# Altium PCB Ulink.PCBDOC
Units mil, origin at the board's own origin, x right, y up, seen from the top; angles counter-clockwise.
Board outline 1950 x 3950 mil, 2 copper layers (Top Layer, Bottom Layer); 42 components, 78 nets, 284 pads, 118 vias.
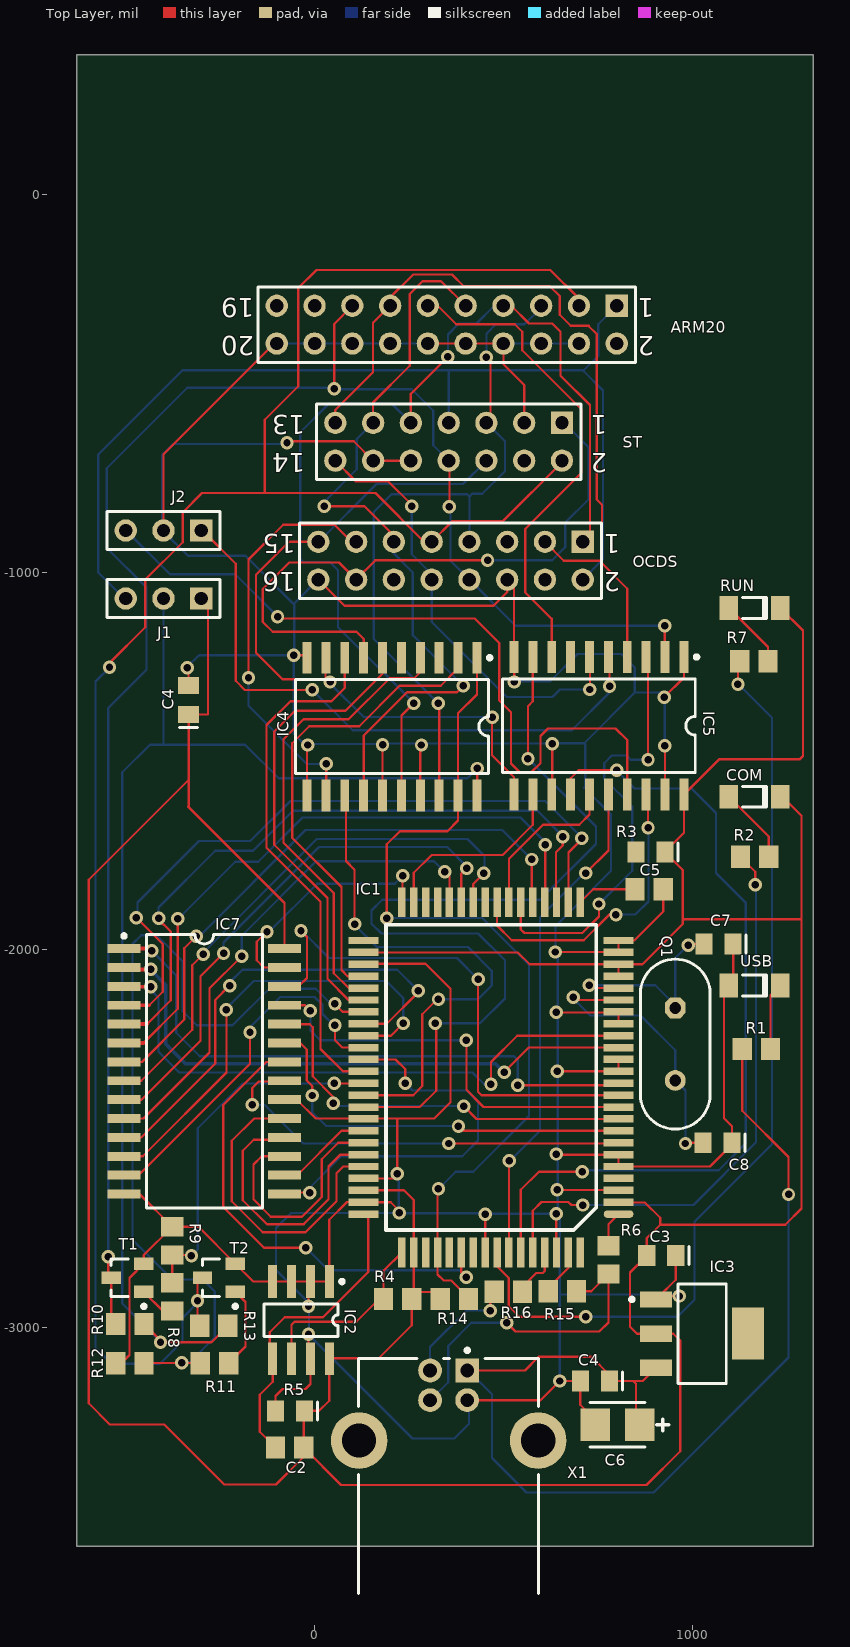
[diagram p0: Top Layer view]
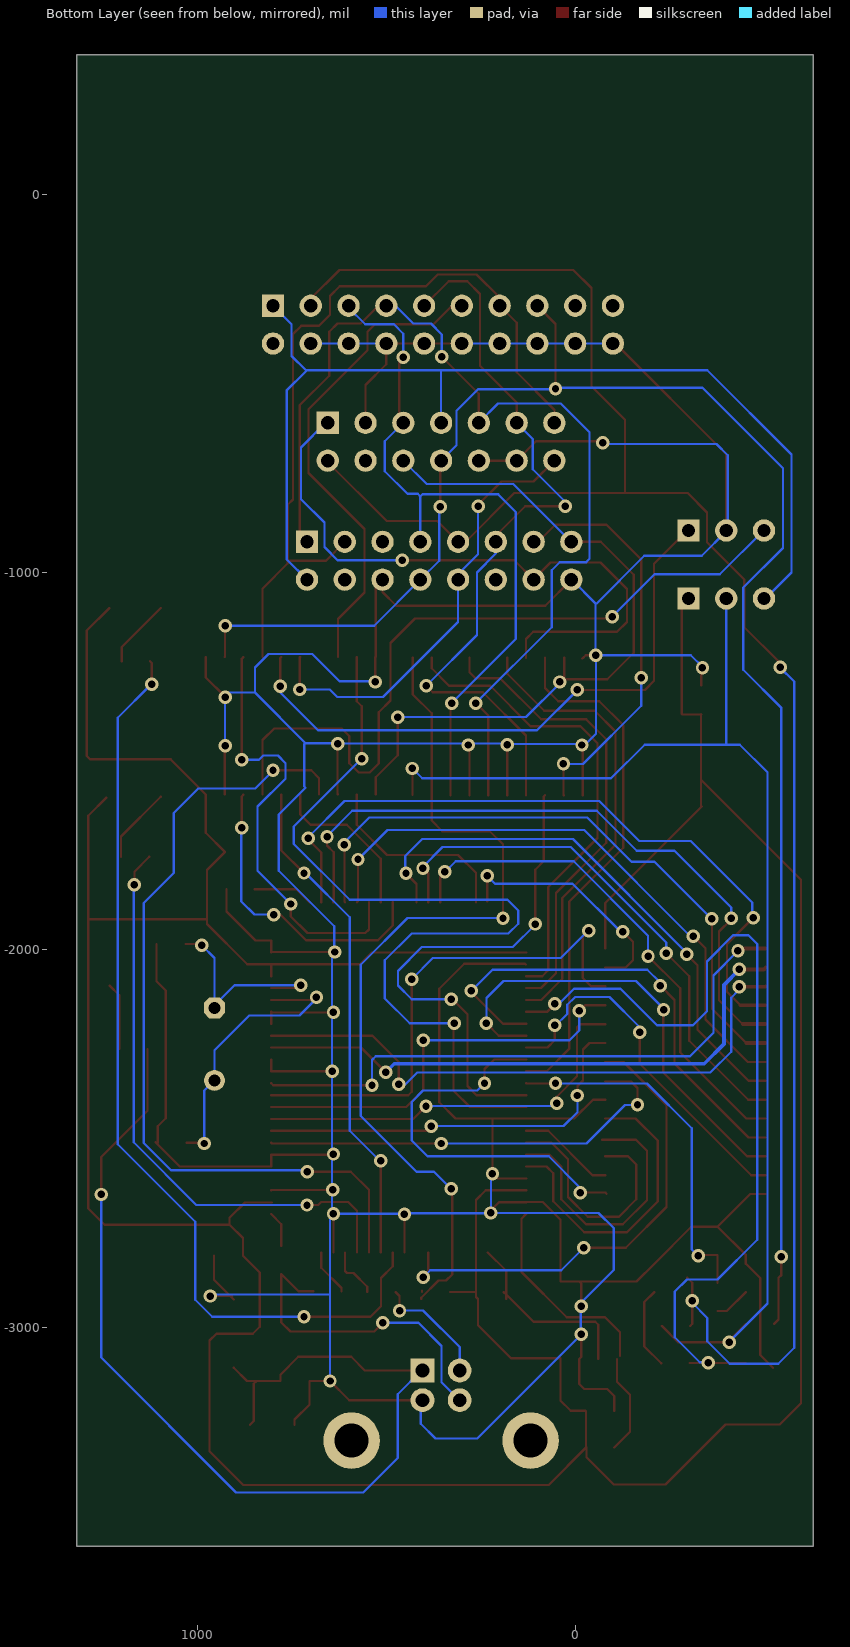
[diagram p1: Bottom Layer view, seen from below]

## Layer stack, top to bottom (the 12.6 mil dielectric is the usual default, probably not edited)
Top Layer: signal copper 1.4
Dielectric: dielectric 12.6, FR-4, Dk 4.8
Bottom Layer: signal copper 1.4

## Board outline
-630,-3580 1320,-3580 1320,120 1320,370 -630,370

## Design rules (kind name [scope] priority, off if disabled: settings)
Clearance [All] p1: gap=6
ComponentClearance [All] p1 off: gap=10 collisioncheckmode=3 verticalgap=10
PolygonConnect [All] p1: connectstyle=Relief reliefconductorwidth=10 reliefentries=4 polygonreliefangle="90 Angle"
RoutingVias [All] p1: holewidth=28 width=50 viastyle="Through Hole" minholewidth=28 minwidth=50 maxholewidth=28 maxwidth=50
SolderMaskExpansion [All] p1: expansion=4
TestPointUsage [All] p1: valid=0 allowmultiple=FALSE
Testpoint [All] p1: side=15 testpointundercomponent=TRUE minsize=40 maxsize=100 preferedsize=60 minholesize=0 maxholesize=40 preferedholesize=32 testpointgrid=1 style=1023 order=0123456789
Width [All] p1: maxlimit=10 minlimit=6 preferedwidth=6
18 further rules are at their usual default settings.

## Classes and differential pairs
component class Ulink: IC4 IC5 IC7

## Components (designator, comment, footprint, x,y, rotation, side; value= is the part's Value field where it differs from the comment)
ARM20 "Comment" HDR2X10 800,-295 r180 top
C2 "Comment" CC2013-0805 -65,-3221 r180 top
C3 "Comment" CC2013-0805 918,-2810 r180 top
C4 "Comment" CC2013-0805 742,-3142 r180 top
C4 "Comment" CC2013-0805 -334,-1339 r90 top
C5 "Comment" CC2013-0805 889,-1741 r180 top
C6 "Comment" "Tant.Cap. 3.5*2.8" 861,-3258 r180 top
C7 "Comment" CC2013-0805 1070,-1985 r180 top
C8 "Comment" CC2013-0805 1067,-2511 r180 top
COM "Comment" DL-35 1165,-1595 r0 top
IC1 "Comment" Quad80 805,-2700 r180 top
IC2 "Comment" SO-8 -36,-2981 r180 top
IC3 "Comment" SOT-223 904,-2926 r270 top
IC4 "SN74LVC244DW" DW020 205,-1409 r180 top (schematic designator U3)
IC5 "SN74LVC244DW" DW020 753,-1407 r180 top (schematic designator U1)
IC7 "CY62256LL-70SNI" S22 -292,-2322 r270 top (schematic designator U2)
J1 "Comment" HDR1X3 -300,-1070 r180 top
J2 "Comment" HDR1X3 -300,-890 r180 top
OCDS "Comment" HDR2X8 710,-920 r180 top
Q1 "Comment" HC-49U 955,-2250 r270 top
R1 "Comment" 2012[0805] 1170,-2263 r0 top
R2 "Comment" 2012[0805] 1165,-1754 r0 top
R3 "Comment" 2012[0805] 886,-1840 r0 top
R4 "Comment" 2012[0805] 220,-2925 r180 top
R5 "Comment" 2012[0805] -66,-3318 r0 top
R6 "Comment" 2012[0805] 778,-2821 r270 top
R7 "Comment" 2012[0805] 1163,-1236 r0 top
R8 "Comment" 2012[0805] -377,-2919 r270 top
R9 "Comment" 2012[0805] -377,-2771 r270 top
R10 "Comment" 2012[0805] -489,-2991 r180 top
R11 "Comment" 2012[0805] -265,-3095 r180 top
R12 "Comment" 2012[0805] -489,-3095 r180 top
R13 "Comment" 2012[0805] -267,-2996 r180 top
R14 "Comment" 2012[0805] 370,-2925 r180 top
R15 "Comment" 2012[0805] 656,-2904 r180 top
R16 "Comment" 2012[0805] 513,-2906 r180 top
RUN "Comment" DL-35 1165,-1095 r0 top
ST "Comment" HDR2X7 655,-605 r180 top
T1 "Comment" SOT23 -452,-2906 r90 top
T2 "Comment" SOT23 -210,-2906 r90 top
USB "Comment" DL-35 1165,-2095 r0 top
X1 "Comment" 1470156 355,-3705 r270 top

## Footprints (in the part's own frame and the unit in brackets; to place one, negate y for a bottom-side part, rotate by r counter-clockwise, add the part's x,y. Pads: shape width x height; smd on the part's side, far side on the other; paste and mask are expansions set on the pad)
2012[0805] [mm] "Chip Resistor; Body 2.0 x 1.3 mm (LxW typ)"
  rect 1.3x1.5 smd: 1(-0.95,0) 2(0.95,0)
1470156 [mm] "Connector; USB1.1, Type B, Thru-Hole; 4 Position; Right Angle"
  rect 1.6x1.6 hole 0.92: 1(-15.01,1.25)
  round 1.6 hole 0.92: 2(-15.01,-1.25) 3(-13.01,-1.25) 4(-13.01,1.25)
  round 3.8 hole 2.3: 5(-10.3,6.02) 6(-10.3,-6.02)
  silkscreen extent -16.48,-6.05 -0.02,6.05
CC2013-0805 [mm] "Chip Capacitor; Body 2.0 x 1.3 mm (LxW typ)"
  rect 1.15x1.4 smd: 1(-0.975,0) 2(0.975,0)
  silkscreen extent -1.85,-0.6 -1.85,0.6
DL-35 [mm] "Metal Electrode Face (MELF) Diode; Body 3.5 x 1.5 mm (LxDia)"
  rect 1.25x1.6 smd: 1(-1.725,0) 2(1.725,0)
  silkscreen extent -0.8,-0.7 0.8,0.7
DW020 [mm] "Plastic Small Outline; 20 Leads; Body Width 7.5 mm"
  rect 0.6x2.15 smd: 1(-5.715,-4.625) 2(-4.445,-4.625) 3(-3.175,-4.625) 4(-1.905,-4.625) 5(-0.635,-4.625) 6(0.635,-4.625) 7(1.905,-4.625) 8(3.175,-4.625) 9(4.445,-4.625) 10(5.715,-4.625) 11(5.715,4.625) 12(4.445,4.625) 13(3.175,4.625) 14(1.905,4.625) 15(0.635,4.625) 16(-0.635,4.625) 17(-1.905,4.625) 18(-3.175,4.625) 19(-4.445,4.625) 20(-5.715,4.625)
  silkscreen extent -6.69,-4.75 6.47,3.15
HC-49U [mm] "Quartz Crystal, Thru-Hole; 2 Leads; Body 11.35 x 4.65 x 13.46 mm (LxWxH max)"
  oct 1.4x1.4 hole 0.8: 1(-2.44,0)
  round 1.4 hole 0.8: 2(2.44,0)
  silkscreen extent -5.71,-2.35 5.71,2.35
HDR1X3 [mm]
  rect 1.5x1.5 hole 0.9: 1(0,0)
  round 1.5 hole 0.9: 2(2.54,0) 3(5.08,0)
  silkscreen extent -1.27,-1.27 6.35,1.27
HDR2X7 [mm]
  rect 1.5x1.5 hole 0.9: 1(0,0)
  round 1.5 hole 0.9: 2(0,2.54) 3(2.54,0) 4(2.54,2.54) 5(5.08,0) 6(5.08,2.54) 7(7.62,0) 8(7.62,2.54) 9(10.16,0) 10(10.16,2.54) 11(12.7,0) 12(12.7,2.54) 13(15.24,0) 14(15.24,2.54)
  silkscreen extent -1.27,-1.27 16.51,3.81
HDR2X8 [mm]
  rect 1.5x1.5 hole 0.9: 1(0,0)
  round 1.5 hole 0.9: 2(0,2.54) 3(2.54,0) 4(2.54,2.54) 5(5.08,0) 6(5.08,2.54) 7(7.62,0) 8(7.62,2.54) 9(10.16,0) 10(10.16,2.54) 11(12.7,0) 12(12.7,2.54) 13(15.24,0) 14(15.24,2.54) 15(17.78,0) 16(17.78,2.54)
  silkscreen extent -1.27,-1.27 19.05,3.81
HDR2X10 [mm]
  rect 1.5x1.5 hole 0.9: 1(0,0)
  round 1.5 hole 0.9: 2(0,2.54) 3(2.54,0) 4(2.54,2.54) 5(5.08,0) 6(5.08,2.54) 7(7.62,0) 8(7.62,2.54) 9(10.16,0) 10(10.16,2.54) 11(12.7,0) 12(12.7,2.54) 13(15.24,0) 14(15.24,2.54) 15(17.78,0) 16(17.78,2.54) 17(20.32,0) 18(20.32,2.54) 19(22.86,0) 20(22.86,2.54)
  silkscreen extent -1.27,-1.27 24.13,3.81
Quad80 [mm]
  oval 2x0.5 smd: 1(0,0)
  rect 2x0.5 smd: 2(0,-0.8) 3(0,-1.6) 4(0,-2.4) 5(0,-3.2) 6(0,-4) 7(0,-4.8) 8(0,-5.6) 9(0,-6.4) 10(0,-7.2) 11(0,-8) 12(0,-8.8) 13(0,-9.6) 14(0,-10.4) 15(0,-11.2) 16(0,-12) 17(0,-12.8) 18(0,-13.6) 19(0,-14.4) 20(0,-15.2) 21(0,-16) 22(0,-16.8) 23(0,-17.6) 24(0,-18.4) 41(17.15,-18.4) 42(17.15,-17.6) 43(17.15,-16.8) 44(17.15,-16) 45(17.15,-15.2) 46(17.15,-14.4) 47(17.15,-13.6) 48(17.15,-12.8) 49(17.15,-12) 50(17.15,-11.2) 51(17.15,-10.4) 52(17.15,-9.6) 53(17.15,-8.8) 54(17.15,-8) 55(17.15,-7.2) 56(17.15,-6.4) 57(17.15,-5.6) 58(17.15,-4.8) 59(17.15,-4) 60(17.15,-3.2) 61(17.15,-2.4) 62(17.15,-1.6) 63(17.15,-0.8) 64(17.15,0)
  rect 0.5x2 smd: 25(2.575,-20.975) 26(3.375,-20.975) 27(4.175,-20.975) 28(4.975,-20.975) 29(5.775,-20.975) 30(6.575,-20.975) 31(7.375,-20.975) 32(8.175,-20.975) 33(8.975,-20.975) 34(9.775,-20.975) 35(10.575,-20.975) 36(11.375,-20.975) 37(12.175,-20.975) 38(12.975,-20.975) 39(13.775,-20.975) 40(14.575,-20.975) 65(14.575,2.575) 66(13.775,2.575) 67(12.975,2.575) 68(12.175,2.575) 69(11.375,2.575) 70(10.575,2.575) 71(9.775,2.575) 72(8.975,2.575) 73(8.175,2.575) 74(7.375,2.575) 75(6.575,2.575) 76(5.775,2.575) 77(4.975,2.575) 78(4.175,2.575) 79(3.375,2.575) 80(2.575,2.575)
  silkscreen extent 1.51,-19.47 15.64,1.07
S22 [mm] "Plastic Small Outline; 28 Leads; Body Width 7.5 mm"
  rect 0.6x2.2 smd: 1(-8.255,-5.4) 2(-6.985,-5.4) 3(-5.715,-5.4) 4(-4.445,-5.4) 5(-3.175,-5.4) 6(-1.905,-5.4) 7(-0.635,-5.4) 8(0.635,-5.4) 9(1.905,-5.4) 10(3.175,-5.4) 11(4.445,-5.4) 12(5.715,-5.4) 13(6.985,-5.4) 14(8.255,-5.4) 15(8.255,5.4) 16(6.985,5.4) 17(5.715,5.4) 18(4.445,5.4) 19(3.175,5.4) 20(1.905,5.4) 21(0.635,5.4) 22(-0.635,5.4) 23(-1.905,5.4) 24(-3.175,5.4) 25(-4.445,5.4) 26(-5.715,5.4) 27(-6.985,5.4) 28(-8.255,5.4)
  silkscreen extent -9.23,-5.52 9.2,3.9
SO-8 [mm] "Small Outline; 8 Leads; Body Width 3.9 mm; Pitch 1.27 mm"
  rect 0.6x2.2 smd: 1(-1.905,-2.6) 2(-0.635,-2.6) 3(0.635,-2.6) 4(1.905,-2.6) 5(1.905,2.6) 6(0.635,2.6) 7(-0.635,2.6) 8(-1.905,2.6)
  silkscreen extent -2.88,-2.72 2.5,1.1
SOT23 [mm] "SOT-23; 3 Leads; Body 3.0 x 2.6 mm, inc. leads (LxW max)"
  rect 0.85x1.3 smd: 1(0,0) 2(1.9,0) 3(0.95,2.2)
  silkscreen extent -1.1,-0.13 2.23,2.2
SOT-223 [mm]
  rect 1.1x2.15 smd: 1(0,0) 2(2.3,0) 3(4.6,0)
  rect 3.5x2.15 smd: 4(2.3,6.2)
  silkscreen extent -1.05,-1.75 5.65,4.72
"Tant.Cap. 3.5*2.8" [mm] "Capacitor, SM Tantalum; Body 3.5 x 2.8 mm (LxW typ)"
  rect 2x2.2 smd: 1(0,0) 2(3,0)
  silkscreen extent -1.93,-1.5 3.35,1.5

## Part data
IC4 IC5: "Octal Buffer/Driver with 3-State Outputs"
IC7: "32K x 8 Static RAM"

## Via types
v1: diameter 35.43, hole 19.68, Top Layer to Bottom Layer, 118 vias

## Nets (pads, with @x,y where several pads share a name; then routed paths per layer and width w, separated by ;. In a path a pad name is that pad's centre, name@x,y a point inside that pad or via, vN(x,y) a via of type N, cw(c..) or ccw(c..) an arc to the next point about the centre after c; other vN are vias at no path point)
+3.3V: C2.1 C3.2 C4.1@-334,-1377.39 C5.1 COM.2 IC1.2 IC1.21 IC1.22 IC1.42 IC1.62 IC1.66 IC2.8 IC3.2 IC5.20 IC7.28 J1.1 R4.1 R5.2 R14.2 RUN.2 | length 10525.2
  Top Layer w6: -335,-1621 -334,-1622 ; C4.1@-334,-1377.39 C4.1@-333,-1377.39 ; C4.1@-333,-1376 C4.1@-333,-1377.39 ; J1.1@-299,-1070 -282,-1087 -282,-1375.77 -283.61,-1377.39 C4.1@-333,-1377.39 ; IC7.28 -79.4,-1876.6 -334,-1622 ; R5.2 -28.6,-3222.98 C2.1 12,-3221 39,-3194 IC2.8 ; IC2.8@39,-3082 170,-3082 257.4,-2994.6 R4.1 262.68,-2919.72 IC1.66 262.68,-2662.68 237.01,-2637.01 IC1.62 ; IC1.42 538.09,-2007.09 569.58,-2038.58 IC1.22 ; R4.1@264.4,-2906 R14.2@330.6,-2906 ; IC1.2@803,-2669 805,-2669 874,-2669 915,-2710 915,-2728 ; IC1.21 IC1.22 ; RUN.2 1293,-1155.09 1293,-1487 1284,-1496 1071.09,-1496 IC5.20 978,-1690.39 C5.1 975,-1788.61 975,-1919 ; COM.2@1241,-1597 1289,-1645 1289,-1919 ; -334,-1622 -333,-1621 -333,-1550 ; -333,-1550 C4.1@-333,-1377.39 ; -333,-1550 -598,-1815 -598,-3201 -542,-3257 -398,-3257 -239,-3416 -102,-3416 -30,-3344 -30,-3318 -30,-3317 -28.8,-3318.2 70,-3417 879,-3417 968,-3328 968,-3035 949.55,-3016.55 IC3.2 853.55,-3016.55 835,-2998 835,-2854.61 C3.2 879.61,-2763.39 915,-2728 ; IC1.22 868.42,-2038.58 975,-1932 975,-1919 ; 915,-2728 1246,-2728 1289,-2685 1289,-1919 ; 975,-1919 1289,-1919
A0: IC1.7 IC7.21 | length 1149.1
  Top Layer w6: v1(-165,-2410) -165,-2366 -148,-2349 IC7.21@-80,-2349 ; v1(355,-2513) 803.02,-2513 IC1.7
  Bottom Layer w6: v1@-165,-2411 -132,-2411 -30,-2513 v1(355,-2513)
A1: IC1.8 IC7.23 | length 1069.2
  Top Layer w6: IC7.23 -38,-2247 -21,-2264 -21,-2346 -6,-2361 v1(-6,-2386) ; v1(381,-2467) 393.53,-2479.53 IC1.8
  Bottom Layer w6: v1(-6,-2386) -6,-2430 31,-2467 v1(381,-2467)
A2: IC1.9 IC7.24 | length 1074.5
  Top Layer w6: IC7.24 -13,-2197 -5,-2205 -5,-2335 49,-2389 v1(49,-2406) ; v1(395,-2414) 429.03,-2448.03 IC1.9
  Bottom Layer w6: v1(49,-2406) 57,-2414 v1(395,-2414)
D0: IC1.48 IC7.11 | length 1272.8
  Top Layer w6: IC7.11 -459,-2497 -263,-2301 -263,-2133 v1(-225,-2095) ; IC1.48 190.94,-2196.06 275,-2112 v1(275,-2109)
  Bottom Layer w6: v1(-225,-2095) -225,-2087 -191,-2053 219,-2053 v1(275,-2109)
D1: IC1.49 IC7.12 | length 1237.3
  Top Layer w6: IC7.12 -455,-2547 -233,-2325 -233,-2160 v1(-234,-2159) ; IC1.49 202.44,-2227.56 v1(235,-2195)
  Bottom Layer w6: v1@-231,-2161 -231,-2159 -231,-2153 -161,-2083 190,-2083 235,-2128 v1(235,-2195)
D2: IC1.50 IC7.13 | length 979.6
  Top Layer w6: IC7.13 -466,-2597 -171,-2302 v1(-171,-2218) ; v1(54,-2200) 54,-2240 73.05,-2259.05 IC1.50
  Bottom Layer w6: v1(-171,-2218) -171,-2205 -91,-2125 0,-2125 21,-2146 21,-2170 52.5,-2201.5 v1@53,-2202
D3: IC1.51 IC7.15 | length 1056.1
  Top Layer w6: IC7.15@-83,-2646 -81.7,-2644.7 -80,-2643 -79.4,-2643 v1(-13,-2643) ; IC1.51 214.55,-2290.55 240,-2316 v1(240,-2354)
  Bottom Layer w6: v1(-13,-2643) -13,-2630 70,-2547 391,-2547 433,-2505 433,-2403 403,-2373 259,-2373 v1(240,-2354)
D4: IC1.57 IC7.16 | length 257.9
  Top Layer w6: IC7.16 -46,-2597 71.47,-2479.53 IC1.57
D5: IC1.58 IC7.17 | length 634.3
  Top Layer w6: IC7.17 -140,-2547 -162,-2569 -162,-2661 -116,-2707 -33,-2707 19,-2655 19,-2555 62.98,-2511.02 IC1.58
D6: IC1.59 IC7.18 | length 734.7
  Top Layer w6: IC7.18@-72,-2503 -79.4,-2503 -161,-2503 -190,-2532 -190,-2663 -126,-2727 -29,-2727 37,-2661 37,-2574 68.48,-2542.52 IC1.59
D7: IC1.60 IC7.19 | length 822.2
  Top Layer w6: IC7.19 -160,-2447 -219,-2506 -219,-2666 -137,-2748 -24,-2748 58,-2666 58,-2592 75.98,-2574.02 IC1.60
D+: R6.2 R15.1 X1.3 | length 863.8
  Top Layer w6: v1(509,-2988) 532,-3011 754,-3011 778,-2987 R6.2 732.4,-2904 R15.1
  Bottom Layer w6: X1.3 306.2,-3192.8 354,-3145 354,-3049 415,-2988 v1@508,-2988
D-: R16.2 X1.2 | length 313.7
  Top Layer w6: v1(465,-2956) 465,-2916.6 R16.2
  Bottom Layer w6: X1.2 305.79,-3052.21 403,-2955 v1@463,-2955
GND: ARM20.4 ARM20.6 ARM20.8 ARM20.10 ARM20.12 ARM20.14 ARM20.16 ARM20.18 ARM20.20 C2.2 C3.1 C4.2 C6.2 C7.1 C8.1 IC1.3 IC1.5 IC1.6 IC1.13 IC1.14 IC1.17 IC1.18 IC1.23 IC1.24 IC1.43 IC1.56 IC1.61 IC1.63 IC1.72 IC1.78 IC2.1 IC2.2 IC2.3 IC2.4 IC2.7 IC3.1 IC4.10 IC4.11 IC4.15 IC4.17 IC5.1 IC5.10 IC5.13 IC5.19 IC7.14 IC7.20 J2.2 OCDS.6 OCDS.16 R3.2 R9.1 R12.2 ST.3 ST.10 ST.12 T1.2 T2.2 USB.1 X1.4 | length 16929.1
  Top Layer w6: R12.2@-524,-3107 -519.2,-3102.2 -490,-3073 -490,-2869.2 T1.2 -452,-2808.6 R9.1 ; IC7.14 -463.6,-2647 R9.1 ; J2.2 -400,-688 -107,-395 ARM20.20 ; v1(-337,-1253) -334,-1256 C4.2@-334,-1300.61 ; C2.2 -103.39,-3181.39 -85,-3163 -24,-3163 -11,-3150 IC2.7 -16,-3078.36 v1(-16,-3018) ; IC7.20 -47,-2397 3,-2447 129.8,-2447 317,-2447 360,-2404 360,-2103 294,-2037 133,-2037 IC1.43@131,-2039 ; v1@-69,-654 104,-654 ST.12 ST.10 ; v1(-55,-1220) -28,-1220 -20.54,-1227.46 IC4.10@-19,-1229 ; IC4.11 v1@-20,-1460 ; v1(-16,-2944) -16,-2883.64 IC2.2 ; OCDS.16 79,-1089 474,-1089 510,-1053 OCDS.6 528,-1038 IC5.10 529,-1225.91 v1(529,-1291) ; IC1.63 201.5,-2668.5 224,-2691 v1(224,-2697) ; IC1.61 206.49,-2605.51 v1(219,-2593) 219,-2448 ; IC1.63@133,-2668 129.8,-2668 86,-2668 39,-2715 IC2.1 IC2.2 ; IC4.15 v1(180,-1457) ; IC4.17 v1@280,-1461 ; ARM20.12 ARM20.10 ARM20.8 500,-450 555,-505 ST.3 ; X1.4 598.2,-3192.8 v1(649,-3142) 703.61,-3142 703.61,-3204.61 742.89,-3243.89 C6.2 ; IC1.72@452,-2801.03 v1(452,-2700) ; IC5.13 629,-1588.09 v1(629,-1455) ; v1(637,-2006) 803.91,-2006 IC1.23 IC1.24 846.41,-1975.59 923.4,-1898.6 R3.2 ; IC1.78@640,-2800.75 v1(640,-2699) ; v1(640,-2541) 641.52,-2542.52 IC1.6 IC1.5 1046.98,-2574.02 1107.69,-2513.31 C8.1@1111,-2510 ; v1(640,-2166) 803.57,-2166 IC1.18 IC1.17 ; v1(642,-2636) 803.99,-2636 IC1.3 ; v1(643,-2322) IC1.13 IC1.13 IC1.14 ; IC3.1 IC3.1@913,-2917 ; IC3.1@908,-2917 IC3.1@913,-2917 ; v1(926,-1331) 978,-1279 IC5.1 ; v1(927,-1460) 928,-1461 IC5.19 ; C3.1 956.39,-2873.61 IC3.1@913,-2917 ; v1(966,-2917) IC3.1@913,-2917 ; C8.1 1105.39,-2467.39 1084,-2446 1084,-2108.09 USB.1 1108.39,-2083.7 C7.1 ; R9.1 -307.6,-2733.6 T2.2 -162.56,-2878.64 IC2.4 IC2.3 IC2.2
  Bottom Layer w6: v1@-337,-1251 -306,-1220 v1(-55,-1220) ; ARM20.20 ARM20.18 ARM20.16 ARM20.14 ARM20.12 ; v1@-72,-656 -73.5,-657.5 -77,-661 -374,-661 -404,-691 -404,-888 -401,-891 -335,-957 -183,-957 -57,-1083 -54,-1083 ; OCDS.16@9,-1020 -54,-1083 ; v1@220,-2593 223,-2596 v1@223,-2697 ; v1(224,-2697) v1@223,-2697 ; X1.4@405,-3194 409,-3198 409,-3255 370,-3294 259,-3294 -15,-3020 -15,-3018 -15,-2945 v1(-16,-2944) -16,-2934 -102,-2848 -102,-2737 -62,-2697 v1@223,-2697 ; ARM20.8 ARM20.6 ARM20.4 ; v1@528,-1289 529,-1289 624,-1289 696,-1217 812,-1217 848,-1253 848,-1319 ; v1(640,-2699) 452,-2699 451,-2699 450,-2698 224,-2698 223,-2698 v1@223,-2697 ; v1(649,-3142) 649,-2913 ; v1(927,-1460) 927,-1332 v1(926,-1331) 914,-1319 848,-1319 ; v1@966,-2918 965.5,-2917.5 961,-2913 649,-2913 ; v1(-55,-1220) -55,-1219 -54,-1218 -54,-1083 ; v1(-55,-1220) -55,-1428 -28,-1455 -18,-1455 180,-1455 182,-1455 183,-1454 283,-1454 626,-1454 627,-1453 629,-1453 714,-1453 ; 649,-2913 649,-2706 642,-2699 644,-2697 644,-2636 644,-2541 644,-2322 644,-2166 644,-2013 638,-2007 638,-2006 638,-1938 785,-1791 785,-1642 714,-1571 717,-1568 717,-1456 714,-1453 ; 714,-1453 848,-1319
  other v1: -18,-1458 283,-1458 -73,-658
IC4_OE: IC1.68 IC4.1 IC4.19 R14.1 | length 2355.3
  Top Layer w6: v1(191,-1917) 191,-1721 226,-1686 352,-1686 380,-1658 IC4.19 380,-1374 430,-1324 IC4.1 ; v1(328,-2633) 325.67,-2635.33 IC1.68 325.67,-2859.67 342,-2876 362,-2876 407.4,-2921.4 R14.1 ; R14.1@405.4,-2906 R14.1@405.4,-2902.4
  Bottom Layer w6: v1@189,-1916 191,-1916 444,-1916 568,-2040 568,-2440 420,-2588 374,-2588 329,-2633 v1(328,-2633)
LCOM: IC1.76 R2.1 | length 1556.4
  Top Layer w6: IC1.76 577.64,-2691.36 601,-2668 672,-2668 680,-2676 v1(710,-2676) ; R2.1 1167,-1793.4 v1(1167,-1828)
  Bottom Layer w6: v1(710,-2676) 1003,-2676 1169,-2510 1169,-1828 v1@1169,-1827
LRUN: IC1.73 R7.1 | length 2490.9
  Top Layer w6: IC1.73 483.15,-2838.15 514,-2869 514,-2944 542,-2972 v1(718,-2972) ; v1(1121,-1297) 1121,-1240.6 R7.1
  Bottom Layer w6: v1(718,-2972) 961,-2972 1006,-2927 1006,-2720 1211,-2515 1211,-1386 v1@1123,-1298
NewNet1: 
NewNet2: IC1.30 IC5.3 | length 1177.2
  Top Layer w6: IC1.30 546.14,-1946.14 556,-1956 709,-1956 753,-1912 v1(753,-1879) ; IC5.3 883,-1229.91 v1(883,-1497)
  Bottom Layer w6: v1(753,-1879) 841,-1791 841,-1621 767,-1547 767,-1506 787,-1486 826,-1486 837,-1497 v1(883,-1497)
NewNet3: ARM20.13 IC5.4 OCDS.3 ST.13 | length 2132.2
  Top Layer w6: ST.13 55,-571 155,-471 155,-340 ARM20.13 200,-273 261,-212 364,-212 395,-243 623,-243 649,-269 649,-319 678,-348 726,-348 726,-349 747,-370 747,-808 761,-822 761,-969 ; OCDS.3 660,-970 760,-970 761,-969 ; IC5.4 828,-1044 761,-977 761,-969
  Bottom Layer w6: ARM20.13 ARM20.13@200,-283
NewNet4: IC5.5 J2.1 | length 1618.5
  Top Layer w6: J2.1 -297,-890 -209,-978 -209,-1288 -185,-1312 v1(-6,-1312) ; IC5.5 781,-1227.91 v1(781,-1302)
  Bottom Layer w6: v1(-6,-1312) 101,-1419 681,-1419 781,-1319 v1(781,-1302)
NewNet5: IC5.6 OCDS.10 ST.14 | length 1178.6
  Top Layer w6: ST.14 110,-760 195,-760 257,-822 v1(257,-826) ; IC5.6 729,-1225.91 v1(729,-1311)
  Bottom Layer w6: v1(257,-826) 257,-953 310,-1006 OCDS.10 310,-1132 509,-1331 630,-1331 650,-1311 v1(729,-1311)
NewNet6: ARM20.11 IC5.8 | length 1294.4
  Top Layer w6: ARM20.11 326,-295 375,-344 530,-344 550,-364 550,-413 706,-569 706,-738 558,-886 558,-1054 628,-1124 IC5.8
NewNet11: IC1.55 IC5.9 | length 2371.5
  Top Layer w6: IC1.55 278.54,-2416.54 322,-2373.07 322,-2197 v1(320,-2195) ; v1(565,-1494) 565,-1355 578,-1342 IC5.9
  Bottom Layer w6: v1(320,-2195) 438,-2195 504,-2129 504,-2028 433,-1957 177,-1957 151,-1931 151,-1896 179,-1868 597,-1868 745,-1720 745,-1674 v1(565,-1494)
NewNet12: IC1.65 IC2.6 R4.2 | length 520.7
  Top Layer w6: IC2.6 -61,-2993 -53,-2985 110.6,-2985 176.6,-2919 R4.2@182.6,-2913 ; R4.2 R4.2@182.6,-2913 ; R4.2@189.6,-2906 R4.2@182.6,-2913 ; IC1.65 182.6,-2849.96 R4.2@182.6,-2913
NewNet14: IC1.32 IC5.18 | length 806.9
  Top Layer w6: IC1.32 483.15,-1936.15 522,-1975 713,-1975 781,-1907 v1(798,-1907) ; IC5.18 883,-1594.09 v1(883,-1677)
  Bottom Layer w6: v1(798,-1907) 849,-1907 884,-1872 884,-1678 v1(883,-1677)
NewNet16: IC1.64 IC2.5 R5.1 | length 815.6
  Top Layer w6: IC2.5@-119,-3076 -119,-3013 -79,-2973 22,-2973 142,-2853 142,-2712 129.9,-2699.9 IC1.64@129,-2699 ; IC2.5 -111,-3144 -145,-3178 -145,-3276.4 R5.1
NewNet17: IC5.17 J2.3 | length 2009.8
  Top Layer w6: v1(-98,-1118) -93,-1123 424,-1123 489,-1188 489,-1340 520,-1371 520,-1507 544,-1531 573,-1531 598,-1506 598,-1434 618,-1414 797,-1414 828,-1445 IC5.17
  Bottom Layer w6: J2.3 -499,-890 -383,-1006 -210,-1006 v1(-98,-1118)
NewNet18: IC1.31 IC5.15 | length 429.7
  Top Layer w6: IC1.31 514.65,-1759.35 605,-1669 701,-1669 728,-1642 IC5.15
NewNet19: IC1.39 IC5.12 | length 525.9
  Top Layer w6: IC1.39 262.68,-1796.32 310,-1749 498,-1749 578,-1669 IC5.12
NewNet20: R8.2 T1.1 | length 95.9
  Top Layer w6: T1.1 -401.6,-2956.4 R8.2
NewNet21: IC4.9 IC5.11 OCDS.15 ST.6 | length 1929
  Top Layer w6: OCDS.15 -68,-920 -155,-1007 -155,-1214 -85,-1284 v1@34,-1284 ; IC4.9@29,-1226 29,-1226.91 29,-1279 v1@34,-1284 ; v1(41,-1291) v1@34,-1284 ; v1(470,-1384) 470,-1485 528,-1543 IC5.11
  Bottom Layer w6: OCDS.15 11,-920 164,-767 393,-767 ST.6 ; v1(41,-1291) 41,-1295 130,-1384 v1(470,-1384)
NewNet22: R11.1 T2.1 | length 218.7
  Top Layer w6: R11.1 -183,-3050.4 -183,-2933 T2.1
NewNet27: IC1.10 IC7.25 | length 1103.2
  Top Layer w6: IC7.25 -26,-2147 v1(-11,-2162) ; v1(402,-2240) 402,-2371 447.54,-2416.54 IC1.10
  Bottom Layer w6: v1(-11,-2162) -11,-2214 15,-2240 v1(402,-2240)
NewNet28: IC1.11 IC7.26 | length 1395.9
  Top Layer w6: IC7.26 -42,-2097 -20,-2075 -20,-1966 v1(-36,-1950) ; v1(433,-2078) 433,-2376 442.04,-2385.04 IC1.11
  Bottom Layer w6: v1(-36,-1950) -34,-1950 38,-2022 377,-2022 v1(433,-2078)
NewNet30: IC1.28 IC7.6 | length 1688.3
  Top Layer w6: -453,-2247 -362,-2156 v1(-362,-1918) ; IC1.28 611,-1872.35 v1(611,-1722)
  Top Layer w10: IC7.6 -453,-2247
  Bottom Layer w6: v1(-362,-1918) -361,-1918 -210,-1767 -149,-1767 -32,-1650 545,-1650 614,-1719 v1@615,-1720
NewNet31: IC1.27 IC7.5 | length 1795.5
  Top Layer w6: -444,-2197 -381,-2134 -381,-1952 v1@-413,-1920 ; IC1.27 639,-1872.58 639,-1742 657,-1724 v1(657,-1701)
  Top Layer w10: IC7.5 -444,-2197 ; v1@-413,-1920 v1(-413,-1917)
  Bottom Layer w6: v1(-413,-1917) -413,-1888 -263,-1738 -163,-1738 -57,-1632 590,-1632 v1@658,-1700
NewNet32: IC1.26 IC7.4 | length 1894.4
  Top Layer w6: v1(-472,-1915) -402,-1985 -402,-2111 -438,-2147 ; IC1.26 672.13,-1742.87 707,-1708 v1(707,-1705)
  Top Layer w10: IC7.4 -438,-2147
  Bottom Layer w6: v1@-469,-1913 -469,-1875 -306,-1712 -170,-1712 -64,-1606 611,-1606 707,-1702 v1(707,-1705)
NewNet33: IC1.16 IC7.3 | length 1592.3
  Top Layer w6: v1(467,-2356) 467,-2297 536.44,-2227.56 IC1.16
  Top Layer w10: IC7.3 -503.6,-2098 v1(-434,-2098)
  Bottom Layer w6: v1@-432,-2098 -432,-2108 -413,-2127 -413,-2270 -358,-2325 418,-2325 449,-2356 v1(467,-2356)
NewNet34: IC1.15 IC7.2 | length 1542.8
  Top Layer w6: v1(502,-2324) 566.95,-2259.05 IC1.15
  Top Layer w10: IC7.2 -499.6,-2052 v1(-434,-2052)
  Bottom Layer w10: v1(-434,-2052) -434,-2053 -394,-2093 -394,-2250 -342,-2302 479,-2302 v1@501,-2324
NewNet35: IC1.1 R6.1 | length 94.8
  Top Layer w6: R6.1 778,-2727 IC1.1
NewNet36: IC1.12 IC7.1 | length 1590.8
  Top Layer w6: v1(538,-2359) 799.54,-2359 IC1.12
  Top Layer w10: IC7.1 -437,-1997 v1(-431,-2003)
  Bottom Layer w6: v1@-428,-2001 -428,-2003 -428,-2006 -366,-2068 -366,-2220 -304,-2282 528,-2282 538,-2292 v1(538,-2359)
NewNet38: IC1.44 IC4.2 | length 1269.4
  Top Layer w6: IC1.44 87.08,-2070.08 71,-2054 71,-1834 -59,-1704 -59,-1453 -14,-1408 118,-1408 225,-1301 334,-1301 380,-1255 IC4.2
NewNet39: IC1.45 IC4.4 | length 1243.1
  Top Layer w6: IC1.45 90.57,-2101.57 51,-2062 51,-1850 -82,-1717 -82,-1443 -29,-1390 90,-1390 199,-1281 264,-1281 280,-1265 IC4.4
NewNet40: IC1.74 IC5.16 | length 1336.5
  Top Layer w6: v1@507.39,-2566.61 v1(515,-2559) 515,-2801.02 IC1.74 ; v1(718,-1797) 778,-1737 IC5.16
  Bottom Layer w6: v1@515,-2561 516,-2560 597,-2479 597,-1914 714,-1797 v1(718,-1797)
NewNet41: IC1.75 IC5.14 | length 2202.9
  Top Layer w6: IC1.75 546.14,-2635.86 594,-2588 v1(709,-2588) ; IC5.14 678,-1546 699,-1525 v1(800,-1525)
  Bottom Layer w6: v1@708,-2584 709,-2584 1070,-2584 1142,-2512 1142,-1876 1063,-1797 1063,-1638 998,-1573 847,-1573 800,-1526 v1(800,-1525)
NewNet42: IC1.46 IC4.6 | length 1224.9
  Top Layer w6: IC1.46 90.07,-2133.07 34,-2077 34,-1863 -107,-1722 -107,-1422 -52,-1367 82,-1367 180,-1269 IC4.6
NewNet43: IC1.77 R16.1 | length 138.9
  Top Layer w6: R16.1 550.4,-2892.6 587,-2856 604,-2856 609.13,-2850.87 IC1.77
NewNet44: IC1.79 R15.2 | length 124.8
  Top Layer w6: R15.2 618.6,-2895.4 672.13,-2841.87 IC1.79
NewNet45: IC4.7 OCDS.14 ST.1 | length 1694.4
  Top Layer w6: IC4.7 130,-1177 111,-1158 -111,-1158 -137,-1132 -137,-1045 -67,-975 65,-975 OCDS.14 161,-969 v1(458,-969)
  Bottom Layer w6: v1(458,-969) 629,-969 664,-934 664,-869 726,-807 726,-670 661,-605 ST.1
NewNet46: IC1.52 IC4.8 | length 1383.2
  Top Layer w6: IC4.8 80,-1307 45,-1342 -64,-1342 -127,-1405 -127,-1730 16,-1873 16,-2263 75.05,-2322.05 IC1.52
NewNet48: ARM20.5 IC4.18 OCDS.7 ST.5 | length 1912.1
  Top Layer w6: IC4.18 v1@330,-1350 ; v1(455,-431) 466,-442 466,-605 ST.5@466,-614
  Bottom Layer w6: v1(327,-1347) 157,-1177 157,-841 204,-794 404,-794 410,-800 ; OCDS.7 410,-800 ; ST.5 504,-654 504,-733 444,-793 417,-793 410,-800 ; v1(455,-431) 455,-369 480,-344 556,-344 600,-300 ARM20.5 ARM20.5@599,-294
NewNet49: 
NewNet50: ARM20.7 IC4.16 OCDS.1 ST.9 | length 2726.9
  Top Layer w6: IC4.16 230,-1380 v1(263,-1347) ; ST.9 255,-528 v1(353,-430) ; ARM20.7@500,-283 ARM20.7 521,-295 568,-342 629,-342 651,-364 651,-480 729,-558 729,-901 OCDS.1
  Bottom Layer w6: ST.9 204,-554 38,-554 -38,-630 -38,-965 -29,-974 41,-974 62,-995 62,-1146 v1(263,-1347) ; v1(353,-430) 353,-371 382,-342 429,-342 476,-295 ARM20.7
NewNet51: ARM20.9 IC4.14 OCDS.11 ST.11 | length 2010.9
  Top Layer w6: v1(26,-826) 132,-826 210,-904 OCDS.11 ; IC4.14 130,-1433 245,-1318 377,-1318 v1(394,-1301) ; ST.11 155,-551 252,-454 252,-264 286,-230 335,-230 ARM20.9
  Bottom Layer w6: v1(26,-826) 26,-814 112,-728 112,-648 ST.11 ; OCDS.11 210,-951 260,-1001 260,-1167 v1(394,-1301)
NewNet52: IC1.54 IC4.13 | length 1376.9
  Top Layer w6: IC4.13 83,-1594.09 83,-1765 106,-1788 v1(106,-1932) ; IC1.54 260.96,-2385.04 285,-2361 285,-2171 325,-2131 v1(328,-2131)
  Bottom Layer w6: v1(106,-1932) 106,-1934 165,-1993 406,-1993 469,-2056 469,-2095 433,-2131 v1(328,-2131)
NewNet53: IC4.12 OCDS.13 | length 1082
  Top Layer w6: v1(-175,-1280) -175,-967 -83,-875 53,-875 98,-920 OCDS.13 ; IC4.12 31,-1590.09 v1(31,-1508)
  Bottom Layer w6: v1(-175,-1280) -175,-1354 -21,-1508 v1(31,-1508)
NewNet54: C8.2 IC1.19 Q1.2 | length 758.3
  Top Layer w6: v1(685,-2126) 692.07,-2133.07 IC1.19 ; v1(982,-2513) 984,-2511 C8.2
  Bottom Layer w6: v1(685,-2126) 685,-2129 730,-2174 863,-2174 955,-2266 Q1.2 982,-2373.06 v1(982,-2513)
NewNet55: C7.2 IC1.20 Q1.1 | length 555
  Top Layer w6: v1(727,-2094) 734.57,-2101.57 IC1.20 ; v1(989,-1988) 992,-1985 C7.2
  Bottom Layer w6: v1(727,-2094) 902,-2094 Q1.1@955,-2147 ; Q1.1 Q1.1@955,-2147 ; v1(989,-1988) 955,-2022 Q1.1@955,-2147
NewNet56: IC1.25 R3.1 | length 159.1
  Top Layer w6: IC1.25 737.83,-1840 R3.1
NewNet58: COM.1 R2.2 | length 202.6
  Top Layer w6: COM.1 1202.4,-1700.32 R2.2
NewNet59: C4.1@780.39,-3142 C6.1 IC3.3 R1.1 X1.1 | length 2784.6
  Top Layer w6: X1.1 556.94,-3114.06 593,-3078 733,-3078 780.39,-3125.39 780.39,-3142 844,-3142 ; C6.1 851,-3248 851,-3149 844,-3142 ; IC3.3 869.1,-3142 844,-3142 ; R1.1 1132.6,-2426.6 1255,-2549 v1(1255,-2648)
  Bottom Layer w6: X1.1 407.06,-3114.06 470,-3177 470,-3346 561,-3437 898,-3437 1255,-3080 v1@1255,-2651
NewNet60: R1.2 USB.2 | length 178.6
  Top Layer w6: R1.2 1207.4,-2120.51 USB.2
NewNet62: R7.2 RUN.1 | length 183.8
  Top Layer w6: RUN.1 1200.4,-1198.32 R7.2
NewNet64: 
NewNet65: IC1.53 R8.1 R9.2 | length 956.5
  Top Layer w6: R8.1 R9.2 v1@-327.6,-2808.4 ; v1(52,-2354) 129.35,-2354 IC1.53
  Bottom Layer w6: v1@-327,-2810 v1(-326,-2810) -325,-2810 -309,-2794 -309,-2473 -190,-2354 v1(52,-2354)
NewNet70: IC1.47 R11.2 R12.1 | length 2307.2
  Top Layer w6: R12.1 -450.6,-3094 v1(-352,-3094) R11.2@-303.4,-3094 ; v1(54,-2143) 54,-2144 74.57,-2164.57 IC1.47
  Bottom Layer w6: v1@-353,-3092 -352,-3092 -330,-3092 -264,-3026 -264,-2905 -296,-2873 -377,-2873 -482,-2768 -482,-1985 -459,-1962 -418,-1962 -349,-2031 -349,-2163 -312,-2200 -217,-2200 -120,-2103 3,-2103 43,-2143 v1(54,-2143)
NewNet71: IC1.36 IC7.10 | length 1360.2
  Top Layer w6: IC7.10 -453,-2447 -278,-2272 -278,-2102 v1(-193,-2017) ; v1(345,-1794) 357.16,-1806.16 IC1.36
  Bottom Layer w6: v1(-193,-2017) -193,-1963 4,-1766 316,-1766 344.5,-1794.5 v1@345,-1795
NewNet72: IC1.35 IC7.9 | length 1422.8
  Top Layer w6: IC7.9 -458,-2397 -302,-2241 -302,-2070 v1(-241,-2009) ; IC1.35 388.66,-1798.34 v1(403,-1784)
  Bottom Layer w6: v1(-241,-2009) -241,-1981 12,-1728 351,-1728 405,-1782 v1@405,-1783
NewNet73: IC1.34 IC7.8 | length 1472.6
  Top Layer w6: IC7.8 -459,-2347 -324,-2212 -324,-2041 v1(-295,-2012) ; IC1.34 420.16,-1825.84 v1(448,-1798)
  Bottom Layer w6: v1(-295,-2012) -295,-2008 6,-1707 405,-1707 450,-1752 v1@450,-1796
NewNet74: IC1.29 IC7.7 | length 1592.7
  Top Layer w6: IC7.7 -457,-2297 -345,-2185 -345,-1996 v1(-313,-1964) ; v1(575,-1761) 575,-1871.57 IC1.29
  Bottom Layer w6: v1(-313,-1964) -305,-1964 -24,-1683 497,-1683 v1(575,-1761) v1@576,-1762
OE: IC1.70 IC7.22 | length 1272
  Top Layer w6: IC7.22 -128,-2297 -242,-2411 -242,-2681 -134,-2789 v1(-23,-2789) ; IC1.70 388.66,-2853.66 v1(402,-2867)
  Bottom Layer w6: v1(-23,-2789) 37,-2849 384,-2849 v1(402,-2867)
RST: ARM20.15 IC5.2 OCDS.8 R10.2 ST.8 T1.3 | length 4736.4
  Top Layer w6: v1(-546,-2813) -546,-2861.21 T1.3 -538.61,-2978.79 R10.2 ; v1(52,-515) 52,-343 ARM20.15 ; v1(357,-827) ST.8@357,-707 ; v1(927,-1142) 927,-1223.91 IC5.2
  Bottom Layer w6: v1(-546,-2813) -546,-1360 -445,-1259 -445,-1041 -550,-936 -550,-725 -337,-512 52,-512 v1@53,-512 ; v1(52,-515) 53,-516 257,-516 314,-573 314,-664 ST.8 ; ARM20.15 ARM20.15@100,-270 ; v1(357,-827) 360,-830 360,-970 OCDS.8 532,-1142 v1(927,-1142)
TRST: ARM20.3 OCDS.9 R13.2 ST.2 T2.3 | length 5403
  Top Layer w6: v1(-543,-1252) -543,-1241 -448,-1146 -448,-1020 -349,-921 -349,-842 -298,-791 -132,-791 ; R13.2 -310,-2990.4 v1(-310,-2929) -310,-2881.98 T2.3 ; ST.2 655,-709 499,-865 365,-865 OCDS.9 290,-920 161,-791 -132,-791 ; ARM20.3 700,-276 624,-200 5,-200 -43,-248 -43,-508 -132,-597 -132,-791
  Bottom Layer w6: v1@-542,-1252 -542.5,-1252.5 -580,-1290 -580,-3054 -538,-3096 -409,-3096 -350,-3037 -350,-2975 -310,-2935 v1(-310,-2929)
VCC: IC4.20 J1.2 R10.1 R13.1 | length 3289.7
  Top Layer w6: R10.1 -408,-3034.6 v1(-408,-3039) -272.6,-3039 R13.1 ; IC4.20@431,-1590.09 v1(431,-1520)
  Bottom Layer w6: v1@-411,-3041 -411,-3039 -411,-3035 -509,-2937 -509,-1530 -436,-1457 -398,-1457 ; J1.2 -400,-1455 -398,-1457 ; v1(431,-1520) 405,-1546 -95,-1546 -184,-1457 -398,-1457
VEXT: ARM20.1 J1.3 OCDS.2 ST.7 | length 2735.5
  Bottom Layer w6: J1.3 -504,-1070 -573,-1001 -573,-689 -350,-466 355,-466 ; ST.7 355,-466 ; OCDS.2 764,-966 764,-519 713,-468 713,-466 ; ARM20.1 751,-344 751,-428 713,-466 ; 355,-466 713,-466
WR: IC1.40 IC7.27 | length 657.3
  Top Layer w6: v1(-126,-1952) -153,-1979 -153,-2028 -134,-2047 IC7.27 ; IC1.40@233,-1872.39 v1(233,-1804)
  Bottom Layer w6: v1(-126,-1952) -120,-1952 7,-1825 212,-1825 v1(233,-1804)
pads on no net: ARM20.2 ARM20.17 ARM20.19 C5.2 IC1.4 IC1.33 IC1.37 IC1.38 IC1.41 IC1.67 IC1.69 IC1.71 IC1.80 IC3.4 IC4.3 IC4.5 IC5.7 OCDS.4 OCDS.5 OCDS.12 ST.4 X1.5 X1.6

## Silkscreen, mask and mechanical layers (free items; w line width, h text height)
Mechanical 1:
  lines w10: -625,-3575 -625,375 1325,375 1325,-3575 -625,-3575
